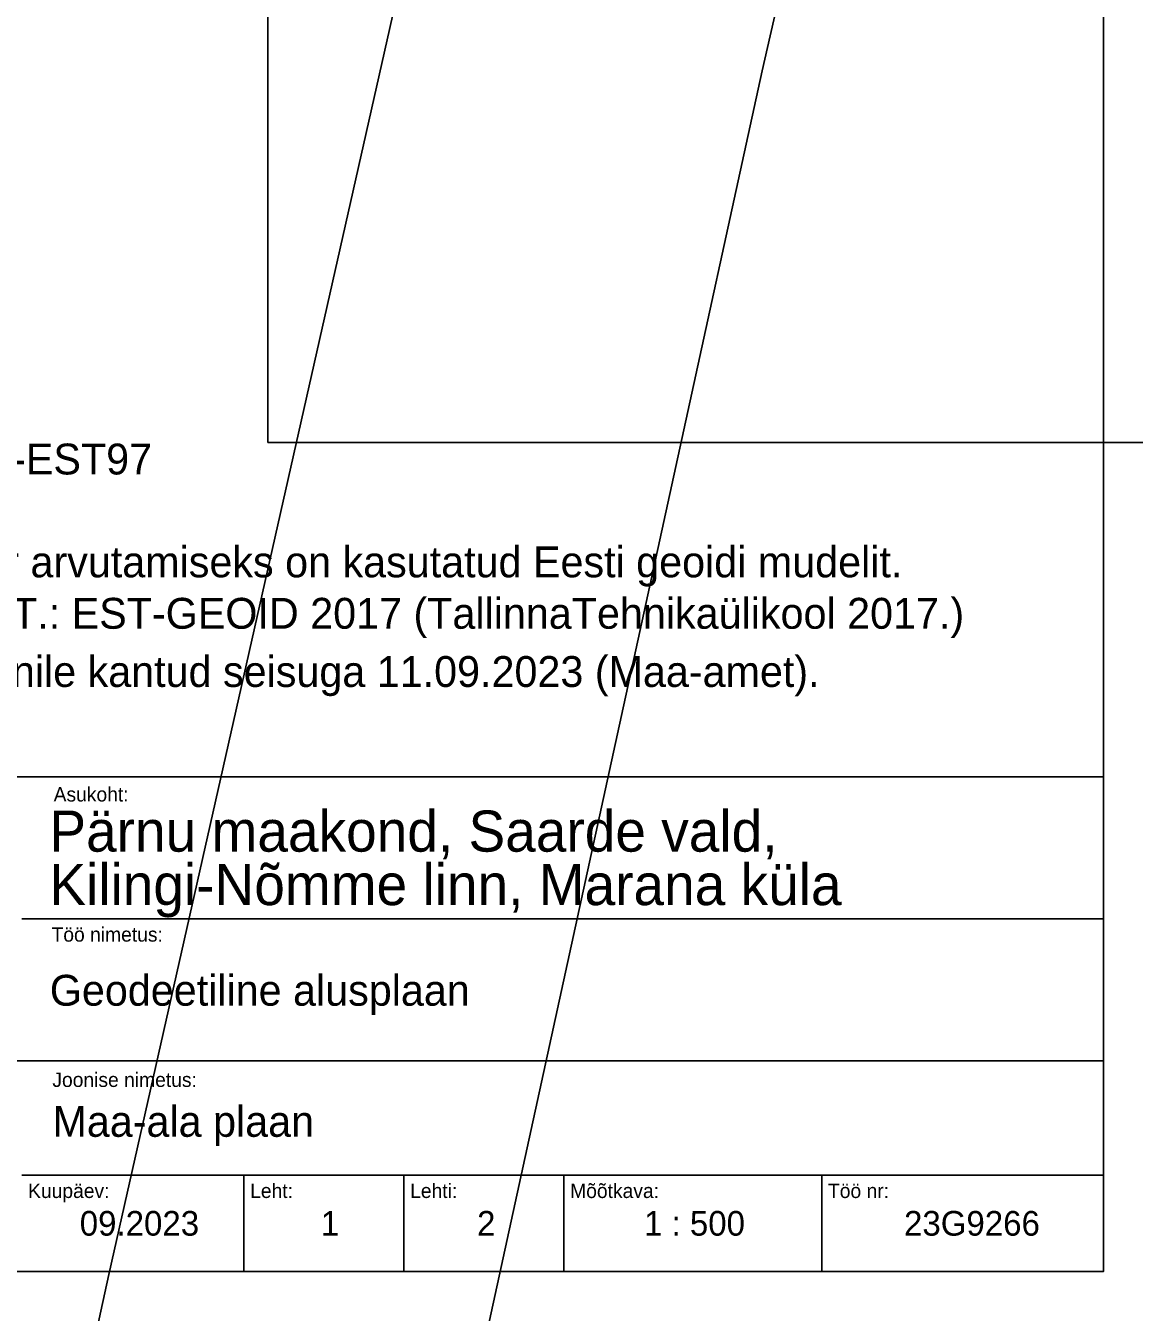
# Model space of a CAD drawing. Extents: x 554846 to 556995, y 6445875 to 6446723.
# Drawn here: x 555521.3 to 555575.2, y 6445972.3 to 6446034.8 of the extents above; entities that cross this region are included whole.
import ezdxf

# ---------------------------------------------------------------- set-up
doc = ezdxf.new("R2010")
doc.units = 0
doc.layers.add('PIIR', color=7, linetype='Continuous')
doc.layers.add('VORMISTUS', color=7, linetype='Continuous')

msp = doc.modelspace()

# ---------------------------------------------------------------- linework, layer by layer
at = {"layer": 'PIIR'}
msp.add_lwpolyline([(555594.35, 6446199.31), (555585.88, 6446161.1), (555573.22, 6446103.15), (555600.27, 6446097.81), (555615.26, 6446094.86), (555613.02, 6446086.06), (555571.23, 6446094.29), (555557.14, 6446032.63), (555543.77, 6445971.36), (555537.75, 6445944.55), (555530.46, 6445911.73), (555512.62, 6445915.68), (555525.38, 6445974.12), (555538.65, 6446032.99), (555544.15, 6446057.37), (555549.98, 6446083.22), (555554.96, 6446105.32), (555562.73, 6446139.8), (555573.2, 6446192.45), (555580.72, 6446194.53)], close=True, dxfattribs=at)
at = {"layer": 'VORMISTUS'}
for p, q in [((555573.727, 6445998.307), (555484.727, 6445998.307)), ((555573.727, 6445998.307), (555573.727, 6445974.267)), ((555573.727, 6445974.267), (555573.727, 6445998.307)), ((555521.157, 6445991.407), (555573.727, 6445991.407)), ((555484.727, 6445984.507), (555573.727, 6445984.507)), ((555521.157, 6445978.937), (555573.727, 6445978.937)), ((555531.947, 6445974.267), (555531.947, 6445978.937)), ((555539.722, 6445974.267), (555539.722, 6445978.937)), ((555547.497, 6445974.267), (555547.497, 6445978.937)), ((555560.027, 6445974.267), (555560.027, 6445978.937)), ((555484.727, 6445974.267), (555573.727, 6445974.267))]:
    msp.add_line(p, q, dxfattribs=at)
for points in [[(556112.613, 6446014.559), (556112.613, 6446428.059), (555533.113, 6446428.059), (555533.113, 6446014.559), (556112.613, 6446014.559)], [(555573.727, 6445974.267), (555573.727, 6446387.767), (554994.227, 6446387.767), (554994.227, 6445974.267), (555573.727, 6445974.267)]]:
    msp.add_lwpolyline(points, dxfattribs=at)
msp.add_lwpolyline([(555484.727, 6445998.307), (555573.727, 6445998.307), (555573.727, 6445974.267), (555484.727, 6445974.267)], close=True, dxfattribs=at)

# ---------------------------------------------------------------- texts
for s, height, p in [('Ristkoordinaatide süsteem: L-EST97 ', 1.5, (555494.821, 6446013.008)), ('Geodeetiliste kõrguste ümber arvutamiseks on kasutatud Eesti geoidi mudelit.', 1.5, (555494.821, 6446008.008)), ('Ellmann, A.; Märdla, S.; Oja, T.: EST-GEOID 2017 (TallinnaTehnikaülikool 2017.)', 1.5, (555494.821, 6446005.508)), ('Katastriüksuste piirid on plaanile kantud seisuga 11.09.2023 (Maa-amet).', 1.5, (555495.031, 6446002.678)), ('Asukoht:', 0.7, (555522.704, 6445997.109)), ('Pärnu maakond, Saarde vald,', 2, (555522.496, 6445994.671)), ('Kilingi-Nõmme linn, Marana küla', 2, (555522.496, 6445992.071)), ('Töö nimetus:', 0.7, (555522.602, 6445990.296)), ('Geodeetiline alusplaan', 1.5, (555522.518, 6445987.182)), ('Joonise nimetus:', 0.7, (555522.642, 6445983.231)), ('Maa-ala plaan', 1.5, (555522.648, 6445980.809)), ('Kuupäev:', 0.7, (555521.463, 6445977.832)), ('Leht:', 0.7, (555532.253, 6445977.832)), ('Lehti:', 0.7, (555540.028, 6445977.832)), ('Mõõtkava:', 0.7, (555547.803, 6445977.832)), ('Töö nr:', 0.7, (555560.333, 6445977.832)), ('09.2023', 1.2, (555523.973, 6445976.002)), ('1', 1.2, (555535.685, 6445976.002)), ('2', 1.2, (555543.28, 6445976.002)), ('1 : 500', 1.2, (555551.392, 6445976.002)), ('23G9266', 1.2, (555564.028, 6445976.002))]:
    msp.add_text(s, height=height, dxfattribs=at).set_placement(p)

doc.saveas('drawing.dxf')
